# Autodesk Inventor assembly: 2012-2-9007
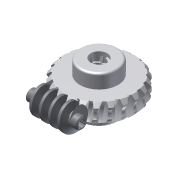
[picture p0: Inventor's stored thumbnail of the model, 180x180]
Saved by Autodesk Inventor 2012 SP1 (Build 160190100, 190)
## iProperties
Created: 2011-12
Part Number: 2012-2-9007
Document SubType Name: Assembly
Designer: Admin
Categories: <?xml version="1.0" encoding="UTF-16"?> <MemberInstance><Categories><FamilyTemplate/><ParamToTemplateMap><ParamToTemplate><ParamToTemplate CategoryParameter="//
ClientObjectVersion: 1
Author: Admin
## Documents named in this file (3)
- D:\Auto Seat Autodesk\New Design\Sub 1\2012-2-9007.iam
- D:\Auto Seat Autodesk\New Design\Sub 1\2012-2-9008.ipt
- D:\Auto Seat Autodesk\New Design\Sub 1\2012-2-9009.ipt
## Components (2 placed, 2 different names)
1. Worm:1 — Rotation:1
2. Worm Gear:1 — Rotation:1
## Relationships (1: RelateRotation 1)
- Rotation:1 [RelateRotation]: Worm:1 ↔ Worm Gear:1
